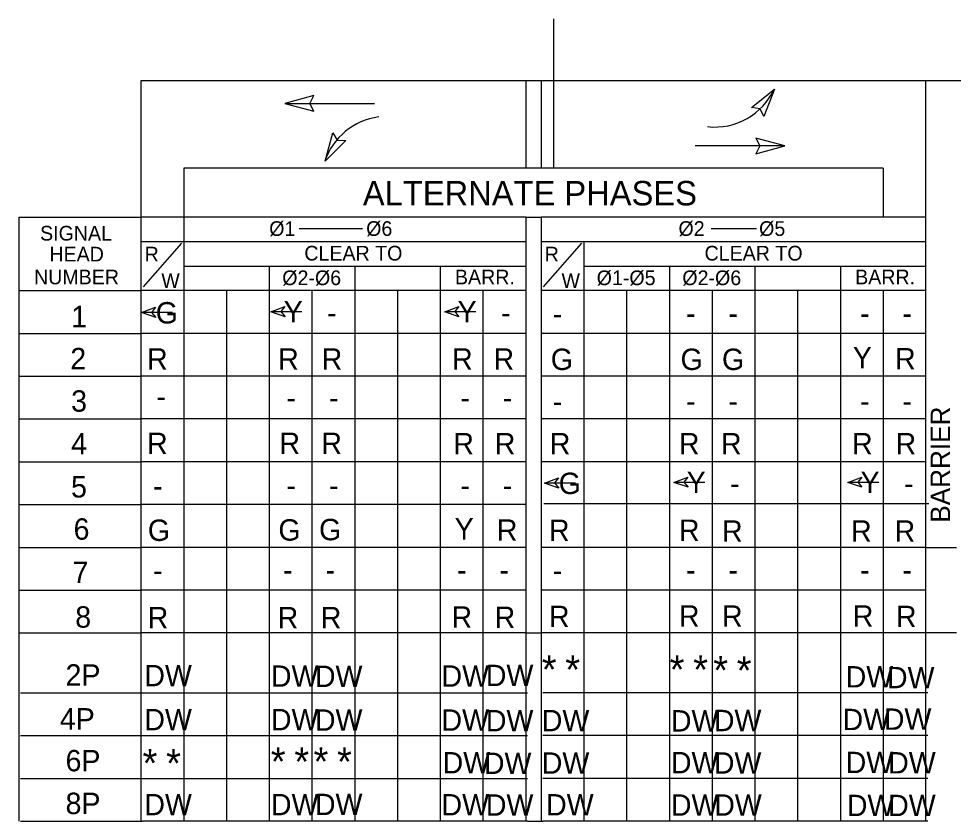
# Model space of a CAD drawing. Extents: x 0 to 3.01, y -0.05 to 1.83.
# Drawn here: x 2.3322 to 2.6407, y 0.997 to 1.2618 of the extents above; entities that cross this region are included whole.
import ezdxf

# ---------------------------------------------------------------- set-up
doc = ezdxf.new("R2010")
doc.units = 0
for name, color, linetype in [('TR_TS_Border', 7, 'Continuous'), ('TR_TS_Phase1', 7, 'Continuous'), ('TR_TS_Phase2', 7, 'Continuous'), ('TR_TS_Phase3', 7, 'Continuous'), ('TR_TS_Phase4', 7, 'Continuous'), ('TR_TS_Phase5', 7, 'Continuous'), ('TR_TS_Phase6', 7, 'Continuous'), ('TR_TS_Phase7', 7, 'Continuous'), ('TR_TS_Phase8', 7, 'Continuous')]:
    doc.layers.add(name, color=color, linetype=linetype)

msp = doc.modelspace()

# ---------------------------------------------------------------- linework, layer by layer
at = {"layer": 'TR_TS_Border'}
for p, q in [((2.5087009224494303, 1.2617748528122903), (2.5087009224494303, 1.2124223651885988)), ((2.372525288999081, 1.241295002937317), (2.372525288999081, 1.19628777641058)), ((2.900955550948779, 1.241295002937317), (2.372525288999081, 1.241295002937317)), ((2.49959746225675, 1.2412949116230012), (2.49959746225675, 1.2124222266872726)), ((2.5046594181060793, 1.2412949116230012), (2.5046594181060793, 1.2124222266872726)), ((2.6317314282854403, 0.9969877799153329), (2.6317314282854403, 1.241295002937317)), ((2.6176005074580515, 1.2124223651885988), (2.3866561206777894, 1.2124223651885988)), ((2.3866561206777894, 1.2124223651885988), (2.3866561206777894, 1.188220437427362)), ((2.6176005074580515, 1.2124223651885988), (2.6176005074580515, 1.19628777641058)), ((2.332189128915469, 1.19628777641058), (2.372525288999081, 1.19628777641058)), ((2.332189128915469, 1.19628777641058), (2.372525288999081, 1.19628777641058)), ((2.332189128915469, 1.19628777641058), (2.332189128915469, 0.9969877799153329)), ((2.4995973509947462, 1.19628777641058), (2.372525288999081, 1.19628777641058)), ((2.372525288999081, 1.19628777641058), (2.372525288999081, 0.9969877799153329)), ((2.4995973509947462, 1.19628777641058), (2.5046592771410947, 1.19628777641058)), ((2.49959746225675, 1.196287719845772), (2.49959746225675, 0.9969876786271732)), ((2.6317314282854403, 1.19628777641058), (2.5046592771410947, 1.19628777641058)), ((2.5046594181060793, 1.196287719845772), (2.5046594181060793, 0.9969876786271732)), ((2.424751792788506, 1.1925441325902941), (2.4457414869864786, 1.1925441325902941)), ((2.560775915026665, 1.1925441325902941), (2.575768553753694, 1.1925441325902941)), ((2.372525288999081, 1.188220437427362), (2.4995973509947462, 1.188220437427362)), ((2.3866561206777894, 1.188220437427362), (2.3866561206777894, 0.9969877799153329)), ((2.5046592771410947, 1.188220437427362), (2.6317314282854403, 1.188220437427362)), ((2.518790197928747, 1.188220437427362), (2.518790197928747, 0.9969877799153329)), ((2.3733690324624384, 1.1732987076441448), (2.386076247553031, 1.1876934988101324)), ((2.505502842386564, 1.1732987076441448), (2.5181573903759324, 1.1876934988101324)), ((2.3866561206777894, 1.1801533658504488), (2.4995973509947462, 1.1801533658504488)), ((2.4149178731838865, 1.1801533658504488), (2.4149178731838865, 0.9969877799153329)), ((2.44312678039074, 1.1801533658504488), (2.44312678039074, 0.9969877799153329)), ((2.4713884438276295, 1.1801533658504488), (2.4713884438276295, 0.9969877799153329)), ((2.518790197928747, 1.1801533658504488), (2.6317314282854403, 1.1801533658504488)), ((2.5469991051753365, 1.1801533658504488), (2.5469991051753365, 0.9969877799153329)), ((2.5752079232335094, 1.1801533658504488), (2.5752079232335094, 0.9969877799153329)), ((2.6034696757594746, 1.1801533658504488), (2.6034696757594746, 0.9969877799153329)), ((2.332189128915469, 1.1720862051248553), (2.372525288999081, 1.1720862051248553)), ((2.332189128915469, 1.1720862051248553), (2.372525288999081, 1.1720862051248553)), ((2.4995973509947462, 1.1720862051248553), (2.372525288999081, 1.1720862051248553)), ((2.4007870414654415, 1.1720862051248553), (2.4007870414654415, 0.9969877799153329)), ((2.428995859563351, 1.1720862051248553), (2.428995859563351, 0.9969877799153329)), ((2.4572576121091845, 1.1720862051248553), (2.4572576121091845, 0.9969877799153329)), ((2.4854665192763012, 1.1720862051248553), (2.4854665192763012, 0.9969877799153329)), ((2.6317314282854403, 1.1720862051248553), (2.5046592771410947, 1.1720862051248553)), ((2.5328681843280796, 1.1720862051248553), (2.5328681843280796, 0.9969877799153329)), ((2.5611299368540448, 1.1720862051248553), (2.5611299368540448, 0.9969877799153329)), ((2.58933884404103, 1.1720862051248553), (2.58933884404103, 0.9969877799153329)), ((2.6176005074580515, 1.1720862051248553), (2.6176005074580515, 0.9969877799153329)), ((2.332189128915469, 1.1579553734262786), (2.372525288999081, 1.1579553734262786)), ((2.4995973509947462, 1.1579553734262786), (2.372525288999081, 1.1579553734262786)), ((2.6317314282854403, 1.1579553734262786), (2.5046592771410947, 1.1579553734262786)), ((2.332189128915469, 1.1438244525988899), (2.372525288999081, 1.1438244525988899)), ((2.4995973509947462, 1.1438244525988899), (2.372525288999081, 1.1438244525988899)), ((2.6317314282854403, 1.1438244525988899), (2.5046592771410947, 1.1438244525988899)), ((2.332189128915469, 1.1297462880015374), (2.372525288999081, 1.1297462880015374)), ((2.4995973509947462, 1.1297462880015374), (2.372525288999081, 1.1297462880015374)), ((2.6317314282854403, 1.1297462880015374), (2.5046592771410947, 1.1297462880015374)), ((2.332189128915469, 1.1156154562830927), (2.372525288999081, 1.1156154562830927)), ((2.4995973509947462, 1.1156154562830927), (2.372525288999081, 1.1156154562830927)), ((2.6317314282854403, 1.1156154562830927), (2.5046592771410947, 1.1156154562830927)), ((2.632634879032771, 1.101687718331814), (2.5055628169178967, 1.101687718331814)), ((2.332189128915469, 1.1014847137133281), (2.372525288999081, 1.1014847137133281)), ((2.4995973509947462, 1.1014847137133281), (2.372525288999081, 1.1014847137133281)), ((2.332189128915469, 1.0873538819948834), (2.372525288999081, 1.0873538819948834)), ((2.4995973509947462, 1.0873538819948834), (2.372525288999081, 1.0873538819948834)), ((2.6317314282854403, 1.0873538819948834), (2.5046592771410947, 1.0873538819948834)), ((2.6317314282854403, 1.0873538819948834), (2.641802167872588, 1.0873538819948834)), ((2.6317314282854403, 1.0591447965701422), (2.6317314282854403, 1.0873538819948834)), ((2.332189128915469, 1.0732230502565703), (2.372525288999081, 1.0732230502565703)), ((2.4995973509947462, 1.0732230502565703), (2.372525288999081, 1.0732230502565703)), ((2.6317314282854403, 1.0732230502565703), (2.5046592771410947, 1.0732230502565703)), ((2.332189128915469, 1.0591447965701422), (2.372525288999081, 1.0591447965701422)), ((2.4995973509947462, 1.0591447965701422), (2.372525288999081, 1.0591447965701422)), ((2.4995973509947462, 1.0591447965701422), (2.5046592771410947, 1.0591447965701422)), ((2.6317314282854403, 1.0591447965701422), (2.5046592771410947, 1.0591447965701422)), ((2.641802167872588, 1.0591447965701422), (2.6317314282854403, 1.0591447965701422)), ((2.3327665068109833, 1.0393805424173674), (2.5001747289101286, 1.0393805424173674)), ((2.6323088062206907, 1.0393805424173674), (2.5052366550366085, 1.0393805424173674)), ((2.3327665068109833, 1.0252497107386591), (2.5001747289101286, 1.0252497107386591)), ((2.6323088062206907, 1.0252497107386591), (2.5052366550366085, 1.0252497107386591)), ((2.3327665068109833, 1.011118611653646), (2.5001747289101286, 1.011118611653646)), ((2.6323088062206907, 1.011118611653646), (2.5052366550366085, 1.011118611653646)), ((2.3327665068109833, 0.9969877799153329), (2.3731024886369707, 0.9969877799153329)), ((2.5001747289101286, 0.9969877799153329), (2.3731024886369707, 0.9969877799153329)), ((2.5001747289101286, 0.9969877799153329), (2.5052366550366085, 0.9969877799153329)), ((2.6323088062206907, 0.9969877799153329), (2.5052366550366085, 0.9969877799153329))]:
    msp.add_line(p, q, dxfattribs=at)
at = {"layer": 'TR_TS_Phase1'}
for p, q in [((2.4333336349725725, 1.2147512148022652), (2.4358523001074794, 1.2241062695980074)), ((2.4358523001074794, 1.2241062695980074), (2.437363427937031, 1.2217317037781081)), ((2.4401699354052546, 1.2215874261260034), (2.4333336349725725, 1.2147512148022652)), ((2.437363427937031, 1.2217317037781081), (2.4401699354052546, 1.2215874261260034)), ((2.372752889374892, 1.1648064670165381), (2.3773874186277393, 1.1665692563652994)), ((2.3773874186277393, 1.1665692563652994), (2.376057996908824, 1.1648652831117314)), ((2.4154498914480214, 1.1650673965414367), (2.4200844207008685, 1.1668301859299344)), ((2.4200844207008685, 1.1668301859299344), (2.4187549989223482, 1.1651261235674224)), ((2.472857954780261, 1.1650673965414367), (2.4774925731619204, 1.1668301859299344)), ((2.4774925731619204, 1.1668301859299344), (2.4761630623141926, 1.1651261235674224)), ((2.3830142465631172, 1.1648064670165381), (2.372752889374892, 1.1648064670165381)), ((2.377431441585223, 1.1631979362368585), (2.372752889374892, 1.1648064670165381)), ((2.376057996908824, 1.1648652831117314), (2.377431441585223, 1.1631979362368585)), ((2.4257110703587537, 1.1650673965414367), (2.4154498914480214, 1.1650673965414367)), ((2.420128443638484, 1.163458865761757), (2.4154498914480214, 1.1650673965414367)), ((2.4187549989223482, 1.1651261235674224), (2.420128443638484, 1.163458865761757)), ((2.4831190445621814, 1.1650673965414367), (2.472857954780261, 1.1650673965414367)), ((2.477536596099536, 1.163458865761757), (2.472857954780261, 1.1650673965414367)), ((2.4761630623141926, 1.1651261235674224), (2.477536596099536, 1.163458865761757))]:
    msp.add_line(p, q, dxfattribs=at)
msp.add_arc((2.4537817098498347, 1.2079166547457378), 0.021617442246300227, 97.19140000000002, 161.63656666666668, dxfattribs=at)
at = {"layer": 'TR_TS_Phase2'}
for p, q in [((2.575534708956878, 1.2223793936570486), (2.5768674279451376, 1.2197880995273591)), ((2.5851593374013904, 1.2197880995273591), (2.575534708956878, 1.2223793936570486)), ((2.5851593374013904, 1.2197880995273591), (2.555539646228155, 1.2197880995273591)), ((2.5768674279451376, 1.2197880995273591), (2.575534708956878, 1.217196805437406)), ((2.575534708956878, 1.217196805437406), (2.5851593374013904, 1.2197880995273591))]:
    msp.add_line(p, q, dxfattribs=at)
at = {"layer": 'TR_TS_Phase5'}
for p, q in [((2.574173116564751, 1.2325265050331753), (2.581713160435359, 1.2385781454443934)), ((2.581713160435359, 1.2385781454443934), (2.5781910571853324, 1.2295529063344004)), ((2.5769471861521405, 1.2320781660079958), (2.574173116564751, 1.2325265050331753)), ((2.5781910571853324, 1.2295529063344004), (2.5769471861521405, 1.2320781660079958)), ((2.505790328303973, 1.1085389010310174), (2.510424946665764, 1.1103016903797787)), ((2.516051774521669, 1.1085389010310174), (2.505790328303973, 1.1085389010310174)), ((2.5104689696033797, 1.1069303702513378), (2.505790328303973, 1.1085389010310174)), ((2.510424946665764, 1.1103016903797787), (2.5090954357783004, 1.1085976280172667)), ((2.5090954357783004, 1.1085976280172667), (2.5104689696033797, 1.1069303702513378)), ((2.54848741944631, 1.108799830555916), (2.553121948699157, 1.1105624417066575)), ((2.5587484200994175, 1.108799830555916), (2.54848741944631, 1.108799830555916)), ((2.553165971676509, 1.1071912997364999), (2.54848741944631, 1.108799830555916)), ((2.553121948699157, 1.1105624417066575), (2.5517925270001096, 1.1088585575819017)), ((2.5517925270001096, 1.1088585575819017), (2.553165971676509, 1.1071912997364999)), ((2.605895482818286, 1.108799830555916), (2.610529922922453, 1.1105624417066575)), ((2.616156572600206, 1.108799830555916), (2.605895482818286, 1.108799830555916)), ((2.610574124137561, 1.1071912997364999), (2.605895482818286, 1.108799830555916)), ((2.610529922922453, 1.1105624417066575), (2.609200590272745, 1.1088585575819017)), ((2.609200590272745, 1.1088585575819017), (2.610574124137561, 1.1071912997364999))]:
    msp.add_line(p, q, dxfattribs=at)
msp.add_arc((2.5620282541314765, 1.2476462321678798), 0.021617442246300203, 263.56145, 335.3874333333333, dxfattribs=at)
at = {"layer": 'TR_TS_Phase6'}
for p, q in [((2.4296520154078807, 1.2364404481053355), (2.4200275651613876, 1.2338492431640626)), ((2.428319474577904, 1.2338492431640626), (2.4296520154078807, 1.2364404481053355)), ((2.4200275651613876, 1.2338492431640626), (2.4296520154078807, 1.2312579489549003)), ((2.4200275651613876, 1.2338492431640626), (2.449647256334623, 1.2338492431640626)), ((2.4296520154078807, 1.2312579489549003), (2.428319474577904, 1.2338492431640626))]:
    msp.add_line(p, q, dxfattribs=at)

# ---------------------------------------------------------------- texts
at = {"layer": 'TR_TS_Border'}
for s, height, rotation, p in [('ALTERNATE PHASES', 0.008066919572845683, 360, (2.445813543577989, 1.2001735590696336)), ('Ø1             Ø6', 0.0048400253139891, 360, (2.4149000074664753, 1.1901184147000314)), ('Ø2          Ø5', 0.0048400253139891, 360, (2.5500184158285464, 1.1901184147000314)), ('SIGNAL', 0.004840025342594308, 360, (2.3392534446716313, 1.1885896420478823)), ('HEAD', 0.004840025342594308, 360, (2.3423278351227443, 1.1816824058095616)), ('R', 0.004840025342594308, 360, (2.373776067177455, 1.1816824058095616)), ('CLEAR TO', 0.004840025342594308, 360, (2.4264937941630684, 1.1819986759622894)), ('R', 0.004840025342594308, 360, (2.5058572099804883, 1.1816824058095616)), ('CLEAR TO', 0.004840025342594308, 360, (2.558627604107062, 1.1819986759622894)), ('NUMBER', 0.004840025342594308, 360, (2.33725081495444, 1.1741426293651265)), ('Ø2-Ø6', 0.004840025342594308, 360, (2.419211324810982, 1.173879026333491)), ('BARR.', 0.004840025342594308, 360, (2.476211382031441, 1.1741426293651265)), ('Ø1-Ø5', 0.004840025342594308, 360, (2.523019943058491, 1.173879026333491)), ('Ø2-Ø6', 0.004840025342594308, 360, (2.5512925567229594, 1.173879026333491)), ('BARR.', 0.004840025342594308, 360, (2.6083451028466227, 1.1741426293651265)), ('W', 0.004840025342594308, 360, (2.379269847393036, 1.1729827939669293)), ('W', 0.004840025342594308, 360, (2.5114041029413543, 1.1729827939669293)), ('BARRIER', 0.006449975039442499, 89.99999722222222, (2.63969352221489, 1.095487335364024))]:
    msp.add_text(s, height=height, rotation=rotation, dxfattribs=at).set_placement(p)
msp.add_text('*', height=0.009384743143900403, dxfattribs=at).set_placement((2.3808567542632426, 1.0114404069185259))
at = {"layer": 'TR_TS_Phase1'}
for s, p in [('1', (2.349556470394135, 1.1600029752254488)), ('G', (2.377430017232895, 1.1612256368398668)), ('Y', (2.419679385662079, 1.16157933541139)), ('Y', (2.477087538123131, 1.16157933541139)), ('-', (2.434049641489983, 1.1612256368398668)), ('-', (2.4914577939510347, 1.1612256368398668)), ('-', (2.508492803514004, 1.1609279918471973)), ('-', (2.5525106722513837, 1.1610840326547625)), ('-', (2.5665449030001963, 1.1610840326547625)), ('-', (2.6099188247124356, 1.1610840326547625)), ('-', (2.6239529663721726, 1.1610840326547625))]:
    msp.add_text(s, height=0.007050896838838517, dxfattribs=at).set_placement(p)
at = {"layer": 'TR_TS_Phase2'}
for s, height, p in [('2', 0.007050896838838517, (2.3492291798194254, 1.1461274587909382)), ('R', 0.007050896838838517, (2.3745659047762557, 1.145999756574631)), ('R', 0.007050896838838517, (2.417849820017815, 1.145999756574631)), ('R', 0.007050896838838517, (2.432203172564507, 1.145999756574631)), ('R', 0.007050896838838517, (2.4752630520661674, 1.145999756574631)), ('R', 0.007050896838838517, (2.488943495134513, 1.145999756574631)), ('G', 0.007050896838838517, (2.5078613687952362, 1.145873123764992)), ('G', 0.007050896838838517, (2.55069685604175, 1.145873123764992)), ('G', 0.007050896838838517, (2.564377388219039, 1.145873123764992)), ('*', 0.009384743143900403, (2.504882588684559, 1.0423992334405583)), ('*', 0.009384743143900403, (2.512652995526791, 1.0423430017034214)), ('*', 0.009384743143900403, (2.5471084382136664, 1.0423954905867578)), ('*', 0.009384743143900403, (2.554878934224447, 1.0423392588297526)), ('*', 0.009384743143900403, (2.5614862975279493, 1.042129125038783)), ('*', 0.009384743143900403, (2.569256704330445, 1.0420728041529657)), ('2P', 0.007050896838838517, (2.3476642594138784, 1.0417379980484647)), ('DW', 0.007050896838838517, (2.37366706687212, 1.0415492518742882)), ('DW', 0.007050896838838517, (2.4154538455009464, 1.0413567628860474)), ('DW', 0.007050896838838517, (2.4299819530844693, 1.0412879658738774)), ('DW', 0.007050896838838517, (2.471768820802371, 1.0413841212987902)), ('DW', 0.007050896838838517, (2.486410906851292, 1.0415766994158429)), ('DW', 0.007050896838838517, (2.6052108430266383, 1.0411299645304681)), ('DW', 0.007050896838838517, (2.6188405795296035, 1.0408934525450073))]:
    msp.add_text(s, height=height, dxfattribs=at).set_placement(p)
for s, p in [('Y', (2.6075875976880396, 1.1464589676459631)), ('R', (2.6215067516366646, 1.1460853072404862))]:
    msp.add_text(s, height=0.007050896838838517, rotation=360, dxfattribs=at).set_placement(p)
at = {"layer": 'TR_TS_Phase3'}
for s, p in [('3', (2.349500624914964, 1.1321247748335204)), ('-', (2.3776819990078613, 1.1336298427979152)), ('-', (2.420586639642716, 1.1332289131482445)), ('-', (2.4346207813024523, 1.1332289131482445)), ('-', (2.477994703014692, 1.1332289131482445)), ('-', (2.492028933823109, 1.1332289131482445)), ('-', (2.508492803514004, 1.13195848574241)), ('-', (2.5525106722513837, 1.1321146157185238)), ('-', (2.5665449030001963, 1.1321146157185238)), ('-', (2.6099188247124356, 1.1321146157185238)), ('-', (2.6239529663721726, 1.1321146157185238))]:
    msp.add_text(s, height=0.007050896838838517, dxfattribs=at).set_placement(p)
at = {"layer": 'TR_TS_Phase4'}
for s, p in [('4', (2.3495008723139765, 1.1180397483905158)), ('R', (2.3745659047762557, 1.1181307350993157)), ('R', (2.4182722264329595, 1.1181955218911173)), ('R', (2.4321061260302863, 1.1181717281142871)), ('R', (2.4756803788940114, 1.1180504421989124)), ('R', (2.4893608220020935, 1.1180504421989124)), ('R', (2.507526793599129, 1.1180504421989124)), ('R', (2.55013806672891, 1.1180504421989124)), ('R', (2.5640427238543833, 1.1180504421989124)), ('R', (2.6073266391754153, 1.1180504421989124)), ('R', (2.6216799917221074, 1.1180504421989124)), ('4P', (2.3457792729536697, 1.0272646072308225)), ('DW', (2.37366706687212, 1.0270192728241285)), ('DW', (2.4154538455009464, 1.0270192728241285)), ('DW', (2.4299819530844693, 1.0268544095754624)), ('DW', (2.471768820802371, 1.0268544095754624)), ('DW', (2.486410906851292, 1.0266618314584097)), ('DW', (2.504881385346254, 1.0266994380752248)), ('DW', (2.5616938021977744, 1.0267161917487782)), ('DW', (2.6041826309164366, 1.0270526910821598)), ('DW', (2.6178119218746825, 1.0271648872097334)), ('DW', (2.547503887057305, 1.0266039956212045))]:
    msp.add_text(s, height=0.007050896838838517, dxfattribs=at).set_placement(p)
at = {"layer": 'TR_TS_Phase5'}
for s, p in [('5', (2.3494727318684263, 1.1038046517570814)), ('G', (2.5104675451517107, 1.104958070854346)), ('Y', (2.5527169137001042, 1.1053117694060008)), ('Y', (2.610125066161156, 1.1053117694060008)), ('-', (2.567087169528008, 1.104958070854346)), ('-', (2.6244953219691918, 1.104958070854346)), ('-', (2.3765687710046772, 1.1041034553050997)), ('-', (2.420586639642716, 1.104259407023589)), ('-', (2.4346207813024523, 1.104259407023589)), ('-', (2.477994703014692, 1.104259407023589)), ('-', (2.492028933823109, 1.104259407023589))]:
    msp.add_text(s, height=0.007050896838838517, dxfattribs=at).set_placement(p)
at = {"layer": 'TR_TS_Phase6'}
for s, height, p in [('6', 0.007050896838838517, (2.3503155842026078, 1.0898872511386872)), ('G', 0.007050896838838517, (2.3748238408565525, 1.0894890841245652)), ('G', 0.007050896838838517, (2.4179289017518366, 1.0895854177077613)), ('G', 0.007050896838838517, (2.4313616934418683, 1.0897060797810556)), ('R', 0.007050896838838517, (2.5072470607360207, 1.0894699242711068)), ('R', 0.007050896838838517, (2.550151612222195, 1.0895024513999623)), ('R', 0.007050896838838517, (2.5643866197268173, 1.0892304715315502)), ('R', 0.007050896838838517, (2.6069978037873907, 1.0892304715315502)), ('R', 0.007050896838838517, (2.6213509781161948, 1.0892304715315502)), ('*', 0.009384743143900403, (2.415420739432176, 1.0120294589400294)), ('*', 0.009384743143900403, (2.423191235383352, 1.0119731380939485)), ('*', 0.009384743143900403, (2.429532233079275, 1.0120294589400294)), ('*', 0.009384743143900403, (2.437302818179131, 1.0119731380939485)), ('6P', 0.007050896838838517, (2.3476642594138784, 1.0134783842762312)), ('*', 0.009384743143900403, (2.373086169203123, 1.0114966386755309)), ('DW', 0.007050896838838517, (2.4721392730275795, 1.0127695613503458)), ('DW', 0.007050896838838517, (2.48576900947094, 1.0125963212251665)), ('DW', 0.007050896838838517, (2.504881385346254, 1.0126718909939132)), ('DW', 0.007050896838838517, (2.547503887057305, 1.0128164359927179)), ('DW', 0.007050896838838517, (2.5616938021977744, 1.0127044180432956)), ('DW', 0.007050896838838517, (2.6052108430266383, 1.0128703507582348)), ('DW', 0.007050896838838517, (2.61923010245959, 1.0127582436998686))]:
    msp.add_text(s, height=height, dxfattribs=at).set_placement(p)
for s, p in [('Y', (2.476120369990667, 1.089953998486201)), ('R', (2.490039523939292, 1.0895479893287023))]:
    msp.add_text(s, height=0.007050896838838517, rotation=360, dxfattribs=at).set_placement(p)
at = {"layer": 'TR_TS_Phase7'}
for s, p in [('7', (2.3499970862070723, 1.075620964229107)), ('-', (2.3765687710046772, 1.076247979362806)), ('-', (2.4194735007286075, 1.076404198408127)), ('-', (2.4335077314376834, 1.076404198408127)), ('-', (2.4768816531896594, 1.076404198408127)), ('-', (2.4909157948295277, 1.076404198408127)), ('-', (2.508492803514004, 1.076247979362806)), ('-', (2.5525106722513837, 1.076404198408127)), ('-', (2.5665449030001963, 1.076404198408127)), ('-', (2.6099188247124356, 1.076404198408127)), ('-', (2.6239529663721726, 1.076404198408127))]:
    msp.add_text(s, height=0.007050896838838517, dxfattribs=at).set_placement(p)
at = {"layer": 'TR_TS_Phase8'}
for s, p in [('8', (2.3508587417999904, 1.0608721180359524)), ('R', (2.3747662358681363, 1.0606523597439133)), ('R', (2.4176708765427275, 1.0606523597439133)), ('R', (2.431905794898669, 1.0606689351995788)), ('R', (2.475078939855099, 1.060844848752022)), ('R', (2.489313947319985, 1.0607652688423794)), ('R', (2.5072470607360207, 1.0610371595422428)), ('R', (2.550151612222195, 1.0611980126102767)), ('R', (2.5643866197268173, 1.0611506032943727)), ('R', (2.6075597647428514, 1.0611980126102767)), ('R', (2.621794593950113, 1.0610384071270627)), ('8P', (2.3476642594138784, 0.9993630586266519)), ('DW', (2.37366706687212, 0.9989912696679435)), ('DW', (2.4154538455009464, 0.9989912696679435)), ('DW', (2.4299819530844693, 0.9990186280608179)), ('DW', (2.471768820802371, 0.9989224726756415)), ('DW', (2.506299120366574, 0.9989138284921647)), ('DW', (2.486410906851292, 0.9988263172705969)), ('DW', (2.547503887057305, 0.9988257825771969)), ('DW', (2.561806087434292, 0.9988257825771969)), ('DW', (2.6056004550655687, 0.9986898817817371)), ('DW', (2.6192298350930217, 0.9986898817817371))]:
    msp.add_text(s, height=0.007050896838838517, dxfattribs=at).set_placement(p)

doc.saveas('drawing.dxf')
